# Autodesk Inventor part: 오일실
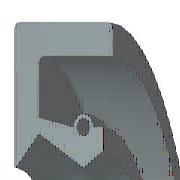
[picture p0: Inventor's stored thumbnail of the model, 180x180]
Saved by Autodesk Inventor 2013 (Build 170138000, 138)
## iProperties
Created: 2014-07
Part Number: 오일실
Material: Rubber
Description: 오일-실
Document SubType Name: Modeling
Standard: KS B 2804
Designer: KYOUNG IL JANG
Standards Organization: KS
Language: ko-KR
Size Designation: D - 10 20 7
Categories: <MemberInstance><Categories><Category DisplayName="샤프트 부품" InternalName="7f7aeb1f-a693-4053-b835-cee3144e0d98" Mnemonic="SHFT"><Category DisplayName="실링" Intern
Density: 0.93 g/cm^3
Mass: 1.11329 g
Surface Area: 16.3871 cm^2
Volume: 1.19708 cm^3
Company: 한국ATC센터
IsCustomPart: 0
Author: KYOUNG IL JANG
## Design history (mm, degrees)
revolve "본체" stored, may be unused: angle "d17" = 90 deg
revolve "스프링1" stored, may be unused: angle "d18" = 90 deg
body "Solid1"
sketch "스케치1"
  geometry: L1 (0, 10)-(7, 10); L2 (7, 8.25)-(1.75, 8.25); L3 (1.75, 6.75)-(4.9, 5); L4 (4.9, 5)-(0, 5); L5 (0, 0)-(9.586, 0) reference; L6 (4.9, 5)-(6.3, 5.875); L7 (0, 18)-(0, -3) reference; L8 (-1.941, 0)-(11.507, 0) reference; L9 (4.2, 7.1)-(1.75, 7.59); L10 (1.75, 7.59)-(1.75, 8.25); L11 (0, 10)-(0, 5.088); L12 (4.9, 5)-(0, 5); L13 (1.75, 6.75)-(0.152, 5.028); L14 (7, 10)-(7, 8.25); L15 (5.6, 7.1)-(6.3, 7.1); L16 (6.3, 7.1)-(6.3, 5.875); C1 r 0.455 at (4.9, 7.1); A1 r 0.7 centre (4.9, 7.1) between (5.6, 7.1) and (4.2, 7.1); A2 r 0.088 centre (0.088, 5.088) between (0, 5.088) and (0.152, 5.028); 1 further point
  constraints: 28 end point, 5 horizontal alignment, 5 point on line, 4 point on circle, 4 vertical alignment, 3 centre point, 3 tangent, 2 collinear, 2 horizontal, 2 perpendicular, 1 coincident, 1 parallel
  dimensions: "d0" = 20 diameter of L1 L5 (= SD2); "d1" = 1.75 distance of L1.end L2.start (= SD); "d2" = 0.91 diameter of C1 (= SPDI); "d3" = 1.4 diameter of A1 (= SPDA); "d4" = 10 diameter of L3.end L5 (= NND); "d5" = 13.5 diameter of L3.start L5 (= TKDM); "d7" = 15.18 diameter of L9.end L5 (= TKDM + 0.24 x SWDT); "d8" = 1.75 distance between parallel lines of L11 L10 (= SD); "d9" = 4.9 distance from line of L11 C1.centre (= SPDST); "d10" = 14.2 diameter of C1.centre L5 (= HLDM); "d11" = 0.0875 radius of A2 (= 0.25 x LAB); "d12" = 6.3 distance between parallel lines of L11 L16 (= SDI); "d13" = 11.75 diameter of L6.end L5 (= ABDM); "d14" = 7 distance from line of L11 L1.end (= SWDT)
fillet "모깎기1" dims "d6" = 0.3 (= RR)
other parameters: "SD2" = 20 [user parameter; used in 1 equation term], "SWDT" = 7 [user parameter; used in 2 equation terms], "RR" = 0.3 [user parameter; used in 1 equation term], "SD" = 1.75 [user parameter; used in 2 equation terms], "NND" = 10 [user parameter; used in 1 equation term], "SPDA" = 1.4 [user parameter; used in 1 equation term], "SPDI" = 0.91 [user parameter; used in 1 equation term], "TKDM" = 13.5 [user parameter; used in 2 equation terms], "HLDM" = 14.2 [user parameter; used in 1 equation term], "ABDM" = 11.75 [user parameter; used in 1 equation term], "SDI" = 6.3 [user parameter; used in 1 equation term], "SPDST" = 4.9 [user parameter; used in 1 equation term], "LAB" = 0.35 [user parameter; used in 1 equation term], "d15" = 0, "d16" = 0, "d19" = 0
